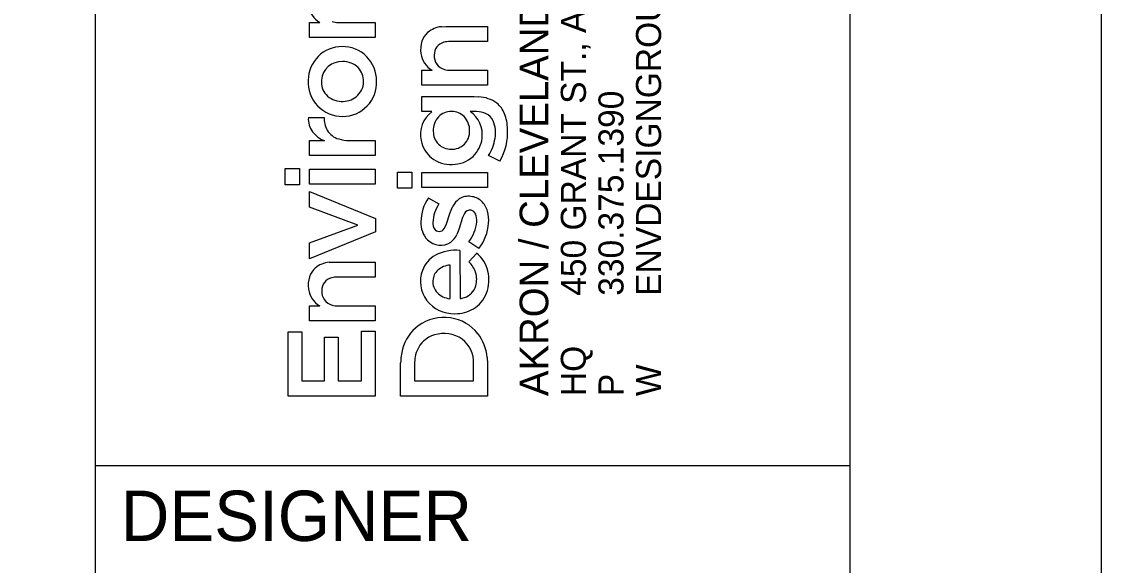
# Model space of a CAD drawing. Extents: x -0.4 to 34, y 0 to 22.
# Drawn here: x 31.853 to 34, y 2.302 to 3.382 of the extents above; entities that cross this region are included whole.
import ezdxf

# ---------------------------------------------------------------- set-up
doc = ezdxf.new("R2010")
doc.units = 0
for name, color, linetype in [('DR_X_Storm_Sewer', 7, 'Continuous'), ('MT_P_Temp_Road', 7, 'Continuous'), ('PF_X_Ground_Line', 7, 'Continuous')]:
    doc.layers.add(name, color=color, linetype=linetype)

msp = doc.modelspace()

# ---------------------------------------------------------------- linework, layer by layer
at = {"layer": 'DR_X_Storm_Sewer'}
for p, q in [((32.4254, 3.3509), (32.4254, 3.3807)), ((32.4254, 3.3807), (32.4455, 3.3807)), ((32.4822, 3.3807), (32.5557, 3.3807)), ((32.5557, 3.3807), (32.5557, 3.351)), ((32.6878, 3.3722), (32.6963, 3.3727)), ((32.6963, 3.3727), (32.7792, 3.3727)), ((32.7792, 3.3727), (32.7792, 3.3429)), ((32.5557, 3.351), (32.4254, 3.3509)), ((32.7792, 3.3429), (32.7048, 3.3428)), ((32.6489, 3.2557), (32.6489, 3.2855)), ((32.6489, 3.2855), (32.669, 3.2855)), ((32.7057, 3.2855), (32.7791, 3.2855)), ((32.7791, 3.2855), (32.7792, 3.2558)), ((32.7792, 3.2558), (32.6489, 3.2557)), ((32.6489, 3.2034), (32.6489, 3.2332)), ((32.6489, 3.2332), (32.7524, 3.2332)), ((32.7524, 3.2332), (32.7619, 3.2329)), ((32.6684, 3.2034), (32.6489, 3.2034)), ((32.7576, 3.2036), (32.7449, 3.2036)), ((32.423, 3.1919), (32.4545, 3.1919)), ((32.4254, 3.1159), (32.4254, 3.1458)), ((32.4254, 3.1458), (32.4547, 3.1458)), ((32.5041, 3.1458), (32.5557, 3.1457)), ((32.5557, 3.1457), (32.5556, 3.1159)), ((32.5556, 3.1159), (32.4254, 3.1159)), ((32.8036, 3.1049), (32.7812, 3.116)), ((32.3771, 3.0582), (32.3771, 3.0903)), ((32.3771, 3.0903), (32.4054, 3.0903)), ((32.4054, 3.0903), (32.4054, 3.0582)), ((32.4254, 3.0594), (32.4254, 3.0893)), ((32.4254, 3.0893), (32.5557, 3.0893)), ((32.5557, 3.0893), (32.5557, 3.0594)), ((32.6005, 3.0511), (32.6005, 3.0832)), ((32.6005, 3.0832), (32.6289, 3.0832)), ((32.6289, 3.0832), (32.6289, 3.0511)), ((32.6489, 3.0523), (32.6489, 3.0822)), ((32.6489, 3.0822), (32.7792, 3.0822)), ((32.7792, 3.0822), (32.7792, 3.0523)), ((32.4054, 3.0582), (32.3771, 3.0582)), ((32.5557, 3.0594), (32.4254, 3.0594)), ((32.6289, 3.0511), (32.6005, 3.0511)), ((32.7792, 3.0523), (32.6489, 3.0523)), ((32.4254, 3.0133), (32.4254, 3.0446)), ((32.4254, 3.0446), (32.5567, 2.9913)), ((32.6615, 3.0321), (32.6827, 3.0203)), ((32.5212, 2.978), (32.4254, 3.0133)), ((32.7048, 3.0026), (32.7104, 3.0153)), ((32.5567, 2.9913), (32.5567, 2.9644)), ((32.6967, 2.9787), (32.7048, 3.0026)), ((32.7298, 2.9933), (32.7221, 2.9688)), ((32.7334, 3.001), (32.7298, 2.9933)), ((32.4254, 2.9429), (32.5212, 2.978)), ((32.5567, 2.9644), (32.4254, 2.9109)), ((32.693, 2.9712), (32.6967, 2.9787)), ((32.7221, 2.9688), (32.7182, 2.9592)), ((32.4254, 2.9109), (32.4254, 2.9429)), ((32.7621, 2.9314), (32.742, 2.9447)), ((32.7245, 2.9275), (32.7246, 2.8319)), ((32.7423, 2.9046), (32.7577, 2.922)), ((32.4644, 2.904), (32.4729, 2.9044)), ((32.4729, 2.9044), (32.5557, 2.9044)), ((32.5557, 2.9044), (32.5557, 2.8746)), ((32.7049, 2.8318), (32.7049, 2.8983)), ((32.5557, 2.8746), (32.4814, 2.8746)), ((32.4254, 2.7875), (32.4254, 2.8173)), ((32.4254, 2.8173), (32.4455, 2.8173)), ((32.4822, 2.8173), (32.5557, 2.8173)), ((32.5557, 2.8173), (32.5557, 2.7876)), ((32.7036, 2.8317), (32.7049, 2.8318)), ((32.5557, 2.7876), (32.4254, 2.7875)), ((32.383, 2.6379), (32.383, 2.766)), ((32.383, 2.766), (32.4101, 2.766)), ((32.4101, 2.766), (32.4101, 2.6683)), ((32.455, 2.6683), (32.455, 2.7549)), ((32.455, 2.7549), (32.4822, 2.7549)), ((32.4822, 2.7549), (32.4822, 2.6683)), ((32.5286, 2.6683), (32.5286, 2.7672)), ((32.5286, 2.7672), (32.5557, 2.7672)), ((32.5557, 2.7672), (32.5557, 2.6379)), ((32.6347, 2.7118), (32.6341, 2.7023)), ((32.7785, 2.715), (32.7792, 2.7021)), ((32.6064, 2.638), (32.6064, 2.704)), ((32.6341, 2.7023), (32.6341, 2.6684)), ((32.7515, 2.6683), (32.7515, 2.7024)), ((32.7792, 2.7021), (32.7792, 2.638)), ((32.4101, 2.6683), (32.455, 2.6683)), ((32.4822, 2.6683), (32.5286, 2.6683)), ((32.6341, 2.6684), (32.7515, 2.6683)), ((32.5557, 2.6379), (32.383, 2.6379)), ((32.7792, 2.638), (32.6064, 2.638))]:
    msp.add_line(p, q, dxfattribs=at)
for points in [[(32.4254, 3.3509), (32.4254, 3.3807), (32.4455, 3.3807)], [(32.4822, 3.3807), (32.5557, 3.3807), (32.5557, 3.351), (32.4254, 3.3509)], [(32.6878, 3.3722), (32.6963, 3.3727), (32.7792, 3.3727), (32.7792, 3.3429), (32.7048, 3.3428)], [(32.6489, 3.2557), (32.6489, 3.2855), (32.669, 3.2855)], [(32.7057, 3.2855), (32.7791, 3.2855), (32.7792, 3.2558), (32.6489, 3.2557)], [(32.6684, 3.2034), (32.6489, 3.2034), (32.6489, 3.2332), (32.7524, 3.2332), (32.7619, 3.2329)], [(32.7576, 3.2036), (32.7449, 3.2036)], [(32.423, 3.1919), (32.4545, 3.1919)], [(32.4254, 3.1159), (32.4254, 3.1458), (32.4547, 3.1458)], [(32.5041, 3.1458), (32.5557, 3.1457), (32.5556, 3.1159), (32.4254, 3.1159)], [(32.8036, 3.1049), (32.7812, 3.116)], [(32.6615, 3.0321), (32.6827, 3.0203)], [(32.693, 2.9712), (32.6967, 2.9787), (32.7048, 3.0026), (32.7104, 3.0153)], [(32.7334, 3.001), (32.7298, 2.9933), (32.7221, 2.9688), (32.7182, 2.9592)], [(32.7621, 2.9314), (32.742, 2.9447)], [(32.7245, 2.9275), (32.7246, 2.8319)], [(32.7423, 2.9046), (32.7577, 2.922)], [(32.4644, 2.904), (32.4729, 2.9044), (32.5557, 2.9044), (32.5557, 2.8746), (32.4814, 2.8746)], [(32.7036, 2.8317), (32.7049, 2.8318), (32.7049, 2.8983)], [(32.4254, 2.7875), (32.4254, 2.8173), (32.4455, 2.8173)], [(32.4822, 2.8173), (32.5557, 2.8173), (32.5557, 2.7876), (32.4254, 2.7875)], [(32.7785, 2.715), (32.7792, 2.7021), (32.7792, 2.638), (32.6064, 2.638)], [(32.6347, 2.7118), (32.6341, 2.7023), (32.6341, 2.6684), (32.7515, 2.6683), (32.7515, 2.7024)], [(32.6064, 2.638), (32.6064, 2.704)]]:
    msp.add_lwpolyline(points, dxfattribs=at)
for points in [[(32.3771, 3.0582), (32.3771, 3.0903), (32.4054, 3.0903), (32.4054, 3.0582)], [(32.4254, 3.0594), (32.4254, 3.0893), (32.5557, 3.0893), (32.5557, 3.0594)], [(32.6005, 3.0511), (32.6005, 3.0832), (32.6289, 3.0832), (32.6289, 3.0511)], [(32.6489, 3.0523), (32.6489, 3.0822), (32.7792, 3.0822), (32.7792, 3.0523)], [(32.4254, 2.9109), (32.4254, 2.9429), (32.5212, 2.978), (32.4254, 3.0133), (32.4254, 3.0446), (32.5567, 2.9913), (32.5567, 2.9644)], [(32.383, 2.6379), (32.383, 2.766), (32.4101, 2.766), (32.4101, 2.6683), (32.455, 2.6683), (32.455, 2.7549), (32.4822, 2.7549), (32.4822, 2.6683), (32.5286, 2.6683), (32.5286, 2.7672), (32.5557, 2.7672), (32.5557, 2.6379)]]:
    msp.add_lwpolyline(points, close=True, dxfattribs=at)
for centre, radius, start, end in [((32.4703, 3.4214), 0.0476, 188.9646, 238.6987), ((32.4703, 3.4214), 0.0476, 188.9646, 238.6987), ((32.4818, 3.4229), 0.0421, 254.0891, 270.5284), ((32.4818, 3.4229), 0.0421, 254.0891, 270.5284), ((32.6922, 3.3225), 0.0499, 94.9706, 130.2248), ((32.6922, 3.3225), 0.0499, 94.9706, 130.2248), ((32.6869, 3.3309), 0.0402, 132.2238, 161.6823), ((32.6869, 3.3309), 0.0402, 132.2238, 161.6823), ((32.4901, 3.2654), 0.0674, 89.8476, 179.6405), ((32.4901, 3.2654), 0.0674, 89.8476, 179.6405), ((32.4906, 3.2647), 0.0681, 359.5401, 90.2114), ((32.4906, 3.2647), 0.0681, 359.5401, 90.2114), ((32.7022, 3.3264), 0.056, 162.274, 187.7917), ((32.7022, 3.3264), 0.056, 162.274, 187.7917), ((32.6983, 3.3169), 0.025, 103.6868, 182.214), ((32.6983, 3.3169), 0.025, 103.6868, 182.214), ((32.7045, 3.2968), 0.046, 89.6051, 105.3303), ((32.7045, 3.2968), 0.046, 89.6051, 105.3303), ((32.6937, 3.3262), 0.0476, 188.9646, 238.6987), ((32.6937, 3.3262), 0.0476, 188.9646, 238.6987), ((32.7008, 3.3138), 0.0276, 175.5844, 255.1382), ((32.7008, 3.3138), 0.0276, 175.5844, 255.1382), ((32.4892, 3.2626), 0.0404, 87.0481, 175.5726), ((32.4892, 3.2626), 0.0404, 87.0481, 175.5726), ((32.492, 3.26), 0.043, 45.8426, 90.9801), ((32.492, 3.26), 0.043, 45.8426, 90.9801), ((32.4946, 3.2642), 0.0382, 357.8857, 44.159), ((32.4946, 3.2642), 0.0382, 357.8857, 44.159), ((32.7053, 3.3277), 0.0421, 254.0891, 270.5284), ((32.7053, 3.3277), 0.0421, 254.0891, 270.5284), ((32.4908, 3.2621), 0.0682, 176.8344, 270.4038), ((32.4908, 3.2621), 0.0682, 176.8344, 270.4038), ((32.4873, 3.2625), 0.0385, 175.1538, 221.1471), ((32.4873, 3.2625), 0.0385, 175.1538, 221.1471), ((32.4912, 3.2614), 0.0675, 270.0624, 2.3776), ((32.4912, 3.2614), 0.0675, 270.0624, 2.3776), ((32.4945, 3.2632), 0.0383, 308.2894, 359.4347), ((32.4945, 3.2632), 0.0383, 308.2894, 359.4347), ((32.4892, 3.2661), 0.0423, 223.0999, 268.8089), ((32.4892, 3.2661), 0.0423, 223.0999, 268.8089), ((32.491, 3.2679), 0.0442, 266.5651, 308.0608), ((32.491, 3.2679), 0.0442, 266.5651, 308.0608), ((32.7591, 3.1679), 0.065, 53.4034, 87.4906), ((32.7591, 3.1679), 0.065, 53.4034, 87.4906), ((32.7029, 3.1581), 0.0569, 127.3748, 192.2247), ((32.7029, 3.1581), 0.0569, 127.3748, 192.2247), ((32.7069, 3.1693), 0.0346, 88.473, 136.4256), ((32.7069, 3.1693), 0.0346, 88.473, 136.4256), ((32.7081, 3.1696), 0.0342, 44.2719, 90.4762), ((32.7081, 3.1696), 0.0342, 44.2719, 90.4762), ((32.7142, 3.1583), 0.0547, 352.1125, 55.923), ((32.7142, 3.1583), 0.0547, 352.1125, 55.923), ((32.7567, 3.1572), 0.0463, 65.0169, 88.8011), ((32.7567, 3.1572), 0.0463, 65.0169, 88.8011), ((32.7652, 3.1804), 0.0514, 21.6075, 50.5577), ((32.7652, 3.1804), 0.0514, 21.6075, 50.5577), ((32.4662, 3.1888), 0.0433, 175.8731, 216.3475), ((32.4662, 3.1888), 0.0433, 175.8731, 216.3475), ((32.5009, 3.1895), 0.0464, 176.9688, 209.6064), ((32.5009, 3.1895), 0.0464, 176.9688, 209.6064), ((32.7114, 3.166), 0.0401, 137.4674, 182.3324), ((32.7114, 3.166), 0.0401, 137.4674, 182.3324), ((32.7037, 3.166), 0.04, 358.5714, 43.5376), ((32.7037, 3.166), 0.04, 358.5714, 43.5376), ((32.7626, 3.1716), 0.0309, 26.2681, 63.803), ((32.7626, 3.1716), 0.0309, 26.2681, 63.803), ((32.7357, 3.1615), 0.0595, 349.3073, 23.4307), ((32.7357, 3.1615), 0.0595, 349.3073, 23.4307), ((32.7307, 3.1671), 0.0884, 1.1514, 21.3627), ((32.7307, 3.1671), 0.0884, 1.1514, 21.3627), ((32.4747, 3.1972), 0.0551, 218.0981, 248.7907), ((32.4747, 3.1972), 0.0551, 218.0981, 248.7907), ((32.4951, 3.1881), 0.0408, 211.9447, 253.2028), ((32.4951, 3.1881), 0.0408, 211.9447, 253.2028), ((32.7065, 3.1637), 0.0351, 178.8821, 271.0837), ((32.7065, 3.1637), 0.0351, 178.8821, 271.0837), ((32.7082, 3.164), 0.0355, 268.2788, 1.5502), ((32.7082, 3.164), 0.0355, 268.2788, 1.5502), ((32.7054, 3.1624), 0.1138, 329.6388, 3.26), ((32.7054, 3.1624), 0.1138, 329.6388, 3.26), ((32.5047, 3.2165), 0.0707, 252.4655, 269.573), ((32.5047, 3.2165), 0.0707, 252.4655, 269.573), ((32.7046, 3.157), 0.0584, 190.7518, 231.2892), ((32.7046, 3.157), 0.0584, 190.7518, 231.2892), ((32.7099, 3.1571), 0.0589, 313.742, 353.8554), ((32.7099, 3.1571), 0.0589, 313.742, 353.8554), ((32.7074, 3.1633), 0.0877, 327.3149, 351.5748), ((32.7074, 3.1633), 0.0877, 327.3149, 351.5748), ((32.7095, 3.159), 0.0605, 269.6361, 312.7088), ((32.7095, 3.159), 0.0605, 269.6361, 312.7088), ((32.7063, 3.1611), 0.0627, 232.4606, 272.5902), ((32.7063, 3.1611), 0.0627, 232.4606, 272.5902), ((32.7364, 2.9826), 0.0897, 146.531, 178.7571), ((32.7364, 2.9826), 0.0897, 146.531, 178.7571), ((32.7466, 2.9971), 0.0405, 125.5118, 153.4159), ((32.7466, 2.9971), 0.0405, 125.5118, 153.4159), ((32.7406, 3.0026), 0.0326, 80.1719, 122.5197), ((32.7406, 3.0026), 0.0326, 80.1719, 122.5197), ((32.7428, 2.9982), 0.0367, 47.7934, 84.6892), ((32.7428, 2.9982), 0.0367, 47.7934, 84.6892), ((32.7452, 2.9789), 0.0749, 146.5112, 176.9101), ((32.7452, 2.9789), 0.0749, 146.5112, 176.9101), ((32.7438, 2.9963), 0.0114, 76.6609, 155.7053), ((32.7438, 2.9963), 0.0114, 76.6609, 155.7053), ((32.744, 2.9951), 0.0126, 21.5098, 78.5262), ((32.744, 2.9951), 0.0126, 21.5098, 78.5262), ((32.7379, 2.9946), 0.0427, 14.9966, 46.2063), ((32.7379, 2.9946), 0.0427, 14.9966, 46.2063), ((32.7259, 2.9877), 0.0321, 354.5726, 22.068), ((32.7259, 2.9877), 0.0321, 354.5726, 22.068), ((32.7104, 2.9867), 0.0712, 355.8306, 15.3914), ((32.7104, 2.9867), 0.0712, 355.8306, 15.3914), ((32.6967, 2.9824), 0.0501, 177.5366, 222.7932), ((32.6967, 2.9824), 0.0501, 177.5366, 222.7932), ((32.6931, 2.9823), 0.0228, 178.4747, 211.0868), ((32.6931, 2.9823), 0.0228, 178.4747, 211.0868), ((32.6833, 2.9767), 0.0115, 212.2368, 268.3777), ((32.6833, 2.9767), 0.0115, 212.2368, 268.3777), ((32.6834, 2.9759), 0.0107, 267.716, 333.7337), ((32.6834, 2.9759), 0.0107, 267.716, 333.7337), ((32.6825, 2.9915), 0.0757, 321.811, 354.7969), ((32.6825, 2.9915), 0.0757, 321.811, 354.7969), ((32.6895, 2.9882), 0.0922, 321.9777, 355.8738), ((32.6895, 2.9882), 0.0922, 321.9777, 355.8738), ((32.686, 2.9753), 0.0375, 225.9854, 302.4797), ((32.686, 2.9753), 0.0375, 225.9854, 302.4797), ((32.681, 2.9758), 0.0408, 308.0877, 335.9874), ((32.681, 2.9758), 0.0408, 308.0877, 335.9874), ((32.7152, 2.8441), 0.0838, 83.615, 118.2876), ((32.7152, 2.8441), 0.0838, 83.615, 118.2876), ((32.7174, 2.8717), 0.0644, 13.5336, 51.3615), ((32.7174, 2.8717), 0.0644, 13.5336, 51.3615), ((32.4687, 2.8543), 0.0499, 94.9696, 130.2225), ((32.4687, 2.8543), 0.0499, 94.9696, 130.2225), ((32.7024, 2.8691), 0.0558, 118.8308, 160.6244), ((32.7024, 2.8691), 0.0558, 118.8308, 160.6244), ((32.7038, 2.8656), 0.0549, 19.0357, 45.4406), ((32.7038, 2.8656), 0.0549, 19.0357, 45.4406), ((32.4635, 2.8626), 0.0402, 132.2219, 161.6818), ((32.4635, 2.8626), 0.0402, 132.2219, 161.6818), ((32.7104, 2.8661), 0.0644, 160.5201, 215.7831), ((32.7104, 2.8661), 0.0644, 160.5201, 215.7831), ((32.7005, 2.8663), 0.0298, 132.9851, 177.179), ((32.7005, 2.8663), 0.0298, 132.9851, 177.179), ((32.7079, 2.8561), 0.0424, 94.008, 130.8817), ((32.7079, 2.8561), 0.0424, 94.008, 130.8817), ((32.7107, 2.8697), 0.047, 344.6059, 17.007), ((32.7107, 2.8697), 0.047, 344.6059, 17.007), ((32.7064, 2.8692), 0.0758, 339.3542, 13.3785), ((32.7064, 2.8692), 0.0758, 339.3542, 13.3785), ((32.4787, 2.8582), 0.056, 162.2736, 187.7919), ((32.4787, 2.8582), 0.056, 162.2736, 187.7919), ((32.4748, 2.8487), 0.025, 103.6865, 182.2187), ((32.4748, 2.8487), 0.025, 103.6865, 182.2187), ((32.4811, 2.8286), 0.046, 89.6049, 105.3284), ((32.4811, 2.8286), 0.046, 89.6049, 105.3284), ((32.7017, 2.865), 0.0311, 175.0013, 223.283), ((32.7017, 2.865), 0.0311, 175.0013, 223.283), ((32.7224, 2.8671), 0.035, 288.0077, 343.5508), ((32.7224, 2.8671), 0.035, 288.0077, 343.5508), ((32.4703, 2.858), 0.0476, 188.962, 238.7037), ((32.4703, 2.858), 0.0476, 188.962, 238.7037), ((32.4773, 2.8456), 0.0276, 175.5854, 255.1439), ((32.4773, 2.8456), 0.0276, 175.5854, 255.1439), ((32.7089, 2.8736), 0.0423, 225.0619, 262.7974), ((32.7089, 2.8736), 0.0423, 225.0619, 262.7974), ((32.7189, 2.8652), 0.0626, 300.9427, 338.7323), ((32.7189, 2.8652), 0.0626, 300.9427, 338.7323), ((32.4818, 2.8595), 0.0422, 254.0916, 270.5284), ((32.4818, 2.8595), 0.0422, 254.0916, 270.5284), ((32.7125, 2.8705), 0.0687, 217.7452, 271.6543), ((32.7125, 2.8705), 0.0687, 217.7452, 271.6543), ((32.7247, 2.8522), 0.0202, 269.7003, 294.8711), ((32.7247, 2.8522), 0.0202, 269.7003, 294.8711), ((32.6923, 2.7079), 0.0864, 81.194, 125.9984), ((32.6923, 2.7079), 0.0864, 81.194, 125.9984), ((32.6946, 2.7113), 0.0827, 37.8521, 82.402), ((32.6946, 2.7113), 0.0827, 37.8521, 82.402), ((32.7155, 2.8724), 0.0706, 269.2048, 300.3341), ((32.7155, 2.8724), 0.0706, 269.2048, 300.3341), ((32.6939, 2.7089), 0.0865, 127.2362, 165.148), ((32.6939, 2.7089), 0.0865, 127.2362, 165.148), ((32.6889, 2.7078), 0.054, 106.1881, 157.3861), ((32.6889, 2.7078), 0.054, 106.1881, 157.3861), ((32.6928, 2.6986), 0.0639, 55.6727, 107.2093), ((32.6928, 2.6986), 0.0639, 55.6727, 107.2093), ((32.6929, 2.705), 0.0587, 357.4662, 52.2665), ((32.6929, 2.705), 0.0587, 357.4662, 52.2665), ((32.6859, 2.7057), 0.0931, 5.7333, 37.304), ((32.6859, 2.7057), 0.0931, 5.7333, 37.304), ((32.7143, 2.7028), 0.1078, 164.7861, 179.3704), ((32.7143, 2.7028), 0.1078, 164.7861, 179.3704), ((32.6983, 2.7039), 0.0641, 157.3571, 172.9275), ((32.6983, 2.7039), 0.0641, 157.3571, 172.9275)]:
    msp.add_arc(centre, radius, start, end, dxfattribs=at)
at = {"layer": 'MT_P_Temp_Road'}
msp.add_lwpolyline([(0, 0), (34, 0), (34, 22), (0, 22)], close=True, dxfattribs=at)
at = {"layer": 'PF_X_Ground_Line'}
for p, q in [((32, 0.5), (32, 21.5)), ((32, 2.5), (33.5, 2.5))]:
    msp.add_line(p, q, dxfattribs=at)
msp.add_lwpolyline([(1.5, 21.5), (33.5, 21.5), (33.5, 0.5), (1.5, 0.5)], close=True, dxfattribs=at)

# ---------------------------------------------------------------- texts
at = {"layer": 'DR_X_Storm_Sewer'}
for s, height, p in [('450 GRANT ST., AKRON, OH  44311', 0.049846, (32.9749, 2.8374)), ('AKRON / CLEVELAND / COLUMBUS', 0.056969, (32.9001, 2.638)), ('ENVDESIGNGROUP.COM', 0.049846, (33.1244, 2.8374)), ('330.375.1390', 0.049846, (33.0497, 2.8374)), ('HQ ', 0.04985, (32.9749, 2.638)), ('W', 0.0498, (33.1244, 2.638)), ('P', 0.0498, (33.0497, 2.638))]:
    msp.add_text(s, height=height, rotation=90, dxfattribs=at).set_placement(p)
msp.add_text('DESIGNER', height=0.1, dxfattribs=at).set_placement((32.05, 2.35))

doc.saveas('drawing.dxf')
